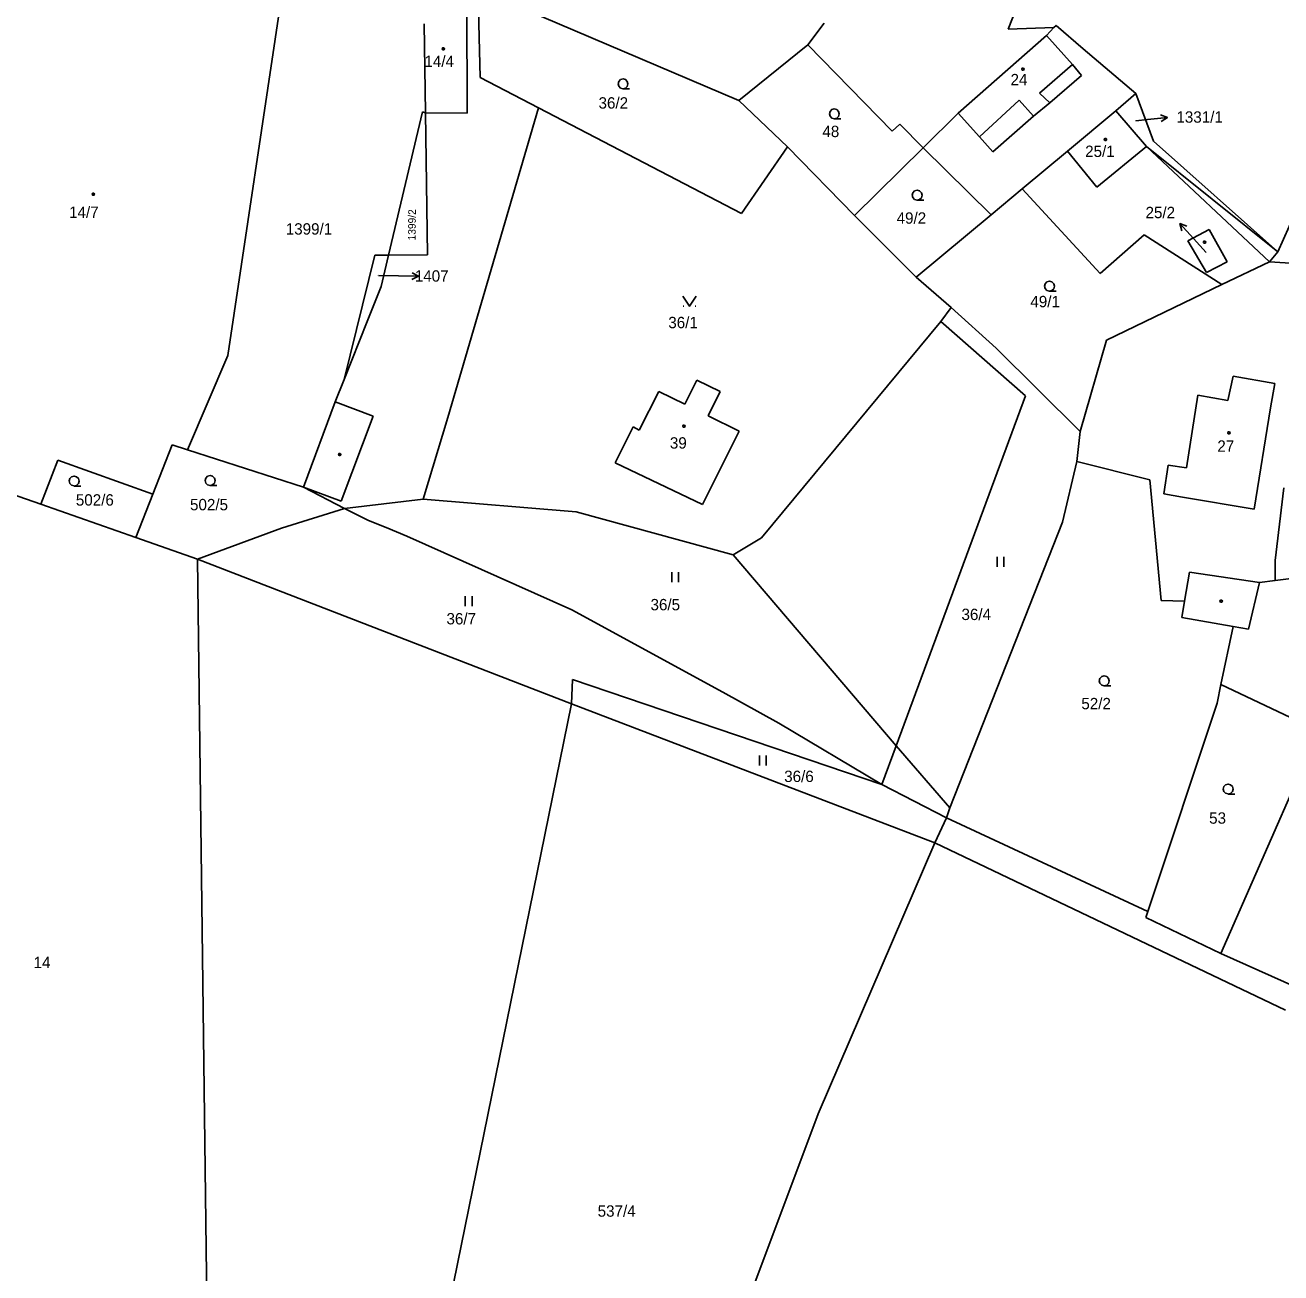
# Model space of a CAD drawing. Extents: x -845995 to -842497, y -1063614 to -1059680.
# Drawn here: x -844636.3 to -844448.3, y -1061712.9 to -1061526.1 of the extents above; entities that cross this region are included whole.
import ezdxf

# ---------------------------------------------------------------- set-up
doc = ezdxf.new("R2010")
doc.units = 0
for name, color, linetype in [('KN_HRANICE', 7, 'Continuous'), ('KN_KULTURY', 7, 'Continuous'), ('KN_PARCELY', 7, 'Continuous'), ('KN_SLUCKY', 7, 'Continuous'), ('KN_STAVEBNI', 7, 'Continuous')]:
    doc.layers.add(name, color=color, linetype=linetype)

# ---------------------------------------------------------------- blocks, each defined once
blk = doc.blocks.new('304')
blk.add_lwpolyline([(0, 0), (-0.38, 0.1), (-0.65, 0.37), (-0.75, 0.74), (-0.65, 1.11), (-0.38, 1.38), (-0.01, 1.48), (0.36, 1.38), (0.63, 1.11), (0.73, 0.73), (0.63, 0.35), (0.36, 0.08), (-0.02, -0.02), (0.98, -0.02)])
blk = doc.blocks.new('306')
for p, q in [((-0.5, 1.5), (-0.5, 0)), ((0.5, 0), (0.5, 1.5))]:
    blk.add_line(p, q)
blk = doc.blocks.new('314')
for p, q in [((-0.95, 0), (-0.85, 0)), ((0.85, 0), (0.95, 0))]:
    blk.add_line(p, q)
blk.add_lwpolyline([(-1, 1.5), (0, 0), (1, 1.5)])
blk = doc.blocks.new('NAHRADNI_SYMBOL')
blk.add_lwpolyline([(0.09, 0.15), (0.18, 0), (0.09, -0.15), (-0.09, -0.15), (-0.18, 0), (-0.09, 0.15), (0.09, 0.15)])
blk = doc.blocks.new('10292')
blk.add_line((0, 3), (0, 0))
blk.add_lwpolyline([(-0.5, 2), (0, 3), (0.5, 2)])
blk = doc.blocks.new('402')
blk.add_lwpolyline([(0.09, 0.15), (0.18, 0), (0.09, -0.15), (-0.09, -0.15), (-0.18, 0), (-0.09, 0.15), (0.09, 0.15)])

msp = doc.modelspace()

# ---------------------------------------------------------------- linework, layer by layer
at = {"layer": 'KN_HRANICE'}
for p, q in [((-844597.26, -1061517.65), (-844605.93, -1061575.54)), ((-844568.5, -1061521.23), (-844568.15, -1061533.97)), ((-844487.27, -1061521.98), (-844489.14, -1061526.71)), ((-844576.55, -1061525.94), (-844576.36, -1061539.23)), ((-844529.43, -1061537.42), (-844559.01, -1061524.82)), ((-844516.66, -1061525.83), (-844519.11, -1061529.08)), ((-844482.29, -1061526.47), (-844481.96, -1061526.18)), ((-844481.96, -1061526.18), (-844477.9, -1061529.66)), ((-844483.41, -1061527.66), (-844496.62, -1061539.27)), ((-844489.14, -1061526.71), (-844482.29, -1061526.47)), ((-844483.41, -1061527.66), (-844482.29, -1061526.47)), ((-844519.11, -1061529.08), (-844529.43, -1061537.42)), ((-844506.52, -1061542.01), (-844519.11, -1061529.08)), ((-844470, -1061536.35), (-844477.9, -1061529.66)), ((-844568.15, -1061533.97), (-844559.45, -1061538.5)), ((-844522.18, -1061544.31), (-844529.43, -1061537.42)), ((-844473.01, -1061538.94), (-844470, -1061536.35)), ((-844470, -1061536.35), (-844467.4, -1061543.5)), ((-844581.88, -1061560.53), (-844576.8, -1061539.11)), ((-844576.8, -1061539.11), (-844576.36, -1061539.23)), ((-844576.36, -1061539.23), (-844576.07, -1061560.49)), ((-844559.45, -1061538.5), (-844573, -1061584.86)), ((-844559.45, -1061538.5), (-844529.07, -1061554.3)), ((-844496.62, -1061539.27), (-844501.88, -1061544.47)), ((-844473.01, -1061538.94), (-844480.27, -1061544.97)), ((-844473.01, -1061538.94), (-844468.42, -1061544.28)), ((-844505.36, -1061540.96), (-844506.52, -1061542.01)), ((-844501.88, -1061544.47), (-844505.36, -1061540.96)), ((-844529.07, -1061554.3), (-844522.18, -1061544.31)), ((-844522.18, -1061544.31), (-844512.12, -1061554.6)), ((-844501.88, -1061544.47), (-844512.12, -1061554.6)), ((-844501.88, -1061544.47), (-844491.7, -1061554.5)), ((-844480.27, -1061544.97), (-844487.06, -1061550.63)), ((-844468.42, -1061544.28), (-844448.75, -1061560.05)), ((-844467.4, -1061543.5), (-844448.75, -1061560.05)), ((-844487.06, -1061550.63), (-844491.7, -1061554.5)), ((-844487.06, -1061550.63), (-844475.34, -1061563.31)), ((-844448.75, -1061560.05), (-844446.24, -1061554.35)), ((-844512.12, -1061554.6), (-844502.89, -1061563.82)), ((-844491.7, -1061554.5), (-844502.89, -1061563.82)), ((-844475.34, -1061563.31), (-844468.77, -1061557.5)), ((-844468.77, -1061557.5), (-844457.13, -1061564.94)), ((-844462.24, -1061558.4), (-844459.06, -1061556.7)), ((-844459.06, -1061556.7), (-844456.35, -1061561.53)), ((-844459.44, -1061563.15), (-844462.24, -1061558.4)), ((-844588.53, -1061579.17), (-844583.92, -1061560.55)), ((-844581.88, -1061560.53), (-844583.92, -1061560.55)), ((-844582.97, -1061565.26), (-844581.88, -1061560.53)), ((-844576.07, -1061560.49), (-844581.88, -1061560.53)), ((-844456.35, -1061561.53), (-844459.44, -1061563.15)), ((-844457.13, -1061564.94), (-844450, -1061561.52)), ((-844448.75, -1061560.05), (-844450, -1061561.52)), ((-844444.59, -1061561.88), (-844450, -1061561.52)), ((-844585.09, -1061570.48), (-844582.97, -1061565.26)), ((-844502.89, -1061563.82), (-844497.68, -1061568.39)), ((-844474.43, -1061573.26), (-844457.13, -1061564.94)), ((-844497.68, -1061568.39), (-844499.22, -1061570.46)), ((-844497.68, -1061568.39), (-844490.94, -1061574.45)), ((-844588.53, -1061579.17), (-844585.09, -1061570.48)), ((-844526.04, -1061602.85), (-844499.22, -1061570.46)), ((-844486.53, -1061581.59), (-844499.22, -1061570.46)), ((-844490.94, -1061574.45), (-844478.36, -1061586.95)), ((-844478.36, -1061586.95), (-844474.43, -1061573.26)), ((-844605.93, -1061575.54), (-844611.99, -1061589.68)), ((-844589.88, -1061582.52), (-844588.53, -1061579.17)), ((-844535.73, -1061579.25), (-844537.53, -1061582.84)), ((-844535.73, -1061579.25), (-844532.24, -1061580.97)), ((-844594.62, -1061595.27), (-844589.88, -1061582.52)), ((-844544.36, -1061586.72), (-844541.4, -1061580.94)), ((-844537.53, -1061582.84), (-844541.4, -1061580.94)), ((-844534.03, -1061584.57), (-844532.24, -1061580.97)), ((-844505.92, -1061633.98), (-844486.53, -1061581.59)), ((-844573, -1061584.86), (-844576.72, -1061597.05)), ((-844547.96, -1061591.63), (-844545.27, -1061586.24)), ((-844545.27, -1061586.24), (-844544.36, -1061586.72)), ((-844529.38, -1061586.87), (-844534.03, -1061584.57)), ((-844633.94, -1061597.82), (-844664.85, -1061586.99)), ((-844534.89, -1061597.88), (-844529.38, -1061586.87)), ((-844478.36, -1061586.95), (-844478.86, -1061591.44)), ((-844614.25, -1061588.91), (-844617.15, -1061596.33)), ((-844611.99, -1061589.68), (-844614.25, -1061588.91)), ((-844611.99, -1061589.68), (-844594.62, -1061595.27)), ((-844631.41, -1061591.24), (-844633.94, -1061597.82)), ((-844617.15, -1061596.33), (-844631.41, -1061591.24)), ((-844547.96, -1061591.63), (-844534.89, -1061597.88)), ((-844478.86, -1061591.44), (-844481.01, -1061600.53)), ((-844478.86, -1061591.44), (-844467.93, -1061594.19)), ((-844594.62, -1061595.27), (-844588.49, -1061598.47)), ((-844467.93, -1061594.19), (-844466.24, -1061612.23)), ((-844447.87, -1061595.38), (-844449.19, -1061606.24)), ((-844617.15, -1061596.33), (-844619.71, -1061602.81)), ((-844588.49, -1061598.47), (-844576.72, -1061597.05)), ((-844576.72, -1061597.05), (-844553.81, -1061598.96)), ((-844619.71, -1061602.81), (-844633.94, -1061597.82)), ((-844597.92, -1061601.39), (-844588.49, -1061598.47)), ((-844584.9, -1061600.24), (-844588.49, -1061598.47)), ((-844553.81, -1061598.96), (-844530.28, -1061605.39)), ((-844582.25, -1061601.32), (-844584.9, -1061600.24)), ((-844579.13, -1061602.62), (-844582.25, -1061601.32)), ((-844481.01, -1061600.53), (-844497.85, -1061643.25)), ((-844610.46, -1061606.05), (-844619.71, -1061602.81)), ((-844610.46, -1061606.05), (-844597.92, -1061601.39)), ((-844554.45, -1061613.63), (-844579.13, -1061602.62)), ((-844530.28, -1061605.39), (-844526.04, -1061602.85)), ((-844610.46, -1061606.05), (-844608.61, -1061754.86)), ((-844554.48, -1061627.7), (-844610.46, -1061606.05)), ((-844449.19, -1061606.24), (-844449.19, -1061609.24)), ((-844434.17, -1061607.4), (-844449.19, -1061609.24)), ((-844451.53, -1061609.53), (-844453.15, -1061616.52)), ((-844449.19, -1061609.24), (-844451.53, -1061609.53)), ((-844466.24, -1061612.23), (-844462.73, -1061612.31)), ((-844463.16, -1061614.78), (-844462.73, -1061612.31)), ((-844531.84, -1061625.95), (-844554.45, -1061613.63)), ((-844455.44, -1061616.12), (-844463.16, -1061614.78)), ((-844457.28, -1061624.8), (-844455.44, -1061616.12)), ((-844453.15, -1061616.52), (-844455.44, -1061616.12)), ((-844554.48, -1061627.7), (-844554.35, -1061624.06)), ((-844554.35, -1061624.06), (-844508.06, -1061639.77)), ((-844457.87, -1061627.58), (-844457.28, -1061624.8)), ((-844442.81, -1061631.67), (-844457.28, -1061624.8)), ((-844523.47, -1061630.59), (-844531.84, -1061625.95)), ((-844468.22, -1061658.79), (-844457.87, -1061627.58)), ((-844582.22, -1061763.64), (-844554.48, -1061627.7)), ((-844500.09, -1061648.51), (-844554.48, -1061627.7)), ((-844508.06, -1061639.77), (-844523.47, -1061630.59)), ((-844508.06, -1061639.77), (-844505.92, -1061633.98)), ((-844445.01, -1061637.13), (-844457.31, -1061665.08)), ((-844508.06, -1061639.77), (-844498.37, -1061644.75)), ((-844497.85, -1061643.25), (-844498.37, -1061644.75)), ((-844498.37, -1061644.75), (-844500.09, -1061648.51)), ((-844498.37, -1061644.75), (-844468.22, -1061658.79)), ((-844517.56, -1061689.06), (-844500.09, -1061648.51)), ((-844447.63, -1061673.57), (-844500.09, -1061648.51)), ((-844468.52, -1061659.69), (-844468.22, -1061658.79)), ((-844457.31, -1061665.08), (-844468.52, -1061659.69)), ((-844438.63, -1061673.4), (-844457.31, -1061665.08)), ((-844539.86, -1061748.43), (-844517.56, -1061689.06))]:
    msp.add_line(p, q, dxfattribs=at)
at = {"layer": 'KN_PARCELY'}
for p, q in [((-844470.04, -1061540.44), (-844468.27, -1061540.25)), ((-844459.49, -1061560.13), (-844461.41, -1061558.03)), ((-844583.39, -1061563.6), (-844580.38, -1061563.65))]:
    msp.add_line(p, q, dxfattribs=at)
at = {"layer": 'KN_SLUCKY'}
for p, q in [((-844570.1, -1061539.27), (-844570.17, -1061523.06)), ((-844483.41, -1061527.66), (-844479.49, -1061532)), ((-844484.42, -1061536.3), (-844479.49, -1061532)), ((-844478.16, -1061533.64), (-844482.92, -1061537.75)), ((-844479.49, -1061532), (-844478.16, -1061533.64)), ((-844493.43, -1061542.82), (-844487.47, -1061537.35)), ((-844487.47, -1061537.35), (-844485.35, -1061539.76)), ((-844482.92, -1061537.75), (-844484.42, -1061536.3)), ((-844576.36, -1061539.23), (-844570.1, -1061539.27)), ((-844493.43, -1061542.82), (-844496.62, -1061539.27)), ((-844482.92, -1061537.75), (-844485.35, -1061539.76)), ((-844485.35, -1061539.76), (-844491.43, -1061545.1)), ((-844491.43, -1061545.1), (-844493.43, -1061542.82)), ((-844475.84, -1061550.39), (-844480.27, -1061544.97)), ((-844468.42, -1061544.28), (-844475.84, -1061550.39)), ((-844450, -1061561.52), (-844468.42, -1061544.28)), ((-844455.44, -1061578.66), (-844456.23, -1061582.31)), ((-844449.21, -1061579.73), (-844455.44, -1061578.66)), ((-844449.84, -1061583.39), (-844449.21, -1061579.73)), ((-844589.88, -1061582.52), (-844584.19, -1061584.62)), ((-844460.74, -1061581.49), (-844462.44, -1061592.38)), ((-844456.23, -1061582.31), (-844460.74, -1061581.49)), ((-844452.33, -1061598.56), (-844449.84, -1061583.39)), ((-844584.19, -1061584.62), (-844588.96, -1061597.37)), ((-844465.16, -1061591.96), (-844465.85, -1061596.27)), ((-844462.44, -1061592.38), (-844465.16, -1061591.96)), ((-844588.96, -1061597.37), (-844594.62, -1061595.27)), ((-844463.04, -1061596.75), (-844465.85, -1061596.27)), ((-844452.33, -1061598.56), (-844463.04, -1061596.75)), ((-844530.28, -1061605.39), (-844505.92, -1061633.98)), ((-844462.73, -1061612.31), (-844461.98, -1061607.98)), ((-844451.53, -1061609.53), (-844461.98, -1061607.98)), ((-844505.92, -1061633.98), (-844497.85, -1061643.25))]:
    msp.add_line(p, q, dxfattribs=at)
at = {"layer": 'KN_STAVEBNI'}
for p, q in [((-844570.1, -1061539.27), (-844570.17, -1061523.06)), ((-844576.55, -1061525.94), (-844576.36, -1061539.23)), ((-844483.41, -1061527.66), (-844496.62, -1061539.27)), ((-844483.41, -1061527.66), (-844479.49, -1061532)), ((-844484.42, -1061536.3), (-844479.49, -1061532)), ((-844493.43, -1061542.82), (-844487.47, -1061537.35)), ((-844487.47, -1061537.35), (-844485.35, -1061539.76)), ((-844482.92, -1061537.75), (-844484.42, -1061536.3)), ((-844576.36, -1061539.23), (-844570.1, -1061539.27)), ((-844493.43, -1061542.82), (-844496.62, -1061539.27)), ((-844482.92, -1061537.75), (-844485.35, -1061539.76)), ((-844473.01, -1061538.94), (-844480.27, -1061544.97)), ((-844473.01, -1061538.94), (-844468.42, -1061544.28)), ((-844475.84, -1061550.39), (-844480.27, -1061544.97)), ((-844468.42, -1061544.28), (-844475.84, -1061550.39)), ((-844455.44, -1061578.66), (-844456.23, -1061582.31)), ((-844449.21, -1061579.73), (-844455.44, -1061578.66)), ((-844535.73, -1061579.25), (-844537.53, -1061582.84)), ((-844535.73, -1061579.25), (-844532.24, -1061580.97)), ((-844449.84, -1061583.39), (-844449.21, -1061579.73)), ((-844544.36, -1061586.72), (-844541.4, -1061580.94)), ((-844537.53, -1061582.84), (-844541.4, -1061580.94)), ((-844534.03, -1061584.57), (-844532.24, -1061580.97)), ((-844460.74, -1061581.49), (-844462.44, -1061592.38)), ((-844456.23, -1061582.31), (-844460.74, -1061581.49)), ((-844452.33, -1061598.56), (-844449.84, -1061583.39)), ((-844547.96, -1061591.63), (-844545.27, -1061586.24)), ((-844545.27, -1061586.24), (-844544.36, -1061586.72)), ((-844529.38, -1061586.87), (-844534.03, -1061584.57)), ((-844534.89, -1061597.88), (-844529.38, -1061586.87)), ((-844547.96, -1061591.63), (-844534.89, -1061597.88)), ((-844465.16, -1061591.96), (-844465.85, -1061596.27)), ((-844462.44, -1061592.38), (-844465.16, -1061591.96)), ((-844463.04, -1061596.75), (-844465.85, -1061596.27)), ((-844452.33, -1061598.56), (-844463.04, -1061596.75))]:
    msp.add_line(p, q, dxfattribs=at)

# ---------------------------------------------------------------- block references
at = {"layer": 'KN_KULTURY'}
for name, p in [('402', (-844573.68, -1061529.66)), ('402', (-844486.93, -1061532.7)), ('304', (-844546.77, -1061535.64)), ('304', (-844515.15, -1061540.13)), ('402', (-844474.57, -1061543.22)), ('NAHRADNI_SYMBOL', (-844626.08, -1061551.43)), ('304', (-844502.75, -1061552.31)), ('NAHRADNI_SYMBOL', (-844459.73, -1061558.6)), ('304', (-844482.94, -1061565.93)), ('314', (-844536.84, -1061568.2)), ('402', (-844537.67, -1061586.12)), ('402', (-844456.09, -1061587.13)), ('402', (-844589.19, -1061590.38)), ('304', (-844628.94, -1061595.08)), ('304', (-844608.58, -1061595.02)), ('306', (-844490.28, -1061607.18)), ('306', (-844539, -1061609.51)), ('306', (-844569.89, -1061613.07)), ('402', (-844457.25, -1061612.33)), ('304', (-844474.74, -1061625)), ('306', (-844525.86, -1061636.94)), ('304', (-844456.2, -1061641.19))]:
    msp.add_blockref(name, p, dxfattribs=at)
at = {"layer": 'KN_PARCELY'}
for p, rotation in [((-844468.27, -1061540.25), -83.77704700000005), ((-844461.41, -1061558.03), 42.341581), ((-844580.38, -1061563.65), -90.99631500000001)]:
    msp.add_blockref('10292', p, dxfattribs=dict(at, rotation=rotation))

# ---------------------------------------------------------------- texts
for s, height, p in [('14/4', 1.7, (-844576.51, -1061532.38)), ('24', 1.7, (-844488.78, -1061535.12)), ('36/2', 1.7, (-844550.45, -1061538.61)), ('1331/1', 1.7, (-844463.95, -1061540.72)), ('48', 1.7, (-844516.94, -1061542.88)), ('1331/1', 0.1, (-844470.32, -1061540.44)), ('25/1', 1.7, (-844477.61, -1061545.85)), ('14/7', 1.7, (-844629.7, -1061554.97)), ('49/2', 1.7, (-844505.83, -1061555.84)), ('25/2', 1.7, (-844468.57, -1061555.01)), ('1399/1', 1.7, (-844597.27, -1061557.47)), ('25/2', 0.1, (-844459.69, -1061560.13)), ('1407', 0.1, (-844583.59, -1061563.65)), ('1407', 1.7, (-844577.95, -1061564.51)), ('49/1', 1.7, (-844485.81, -1061568.34)), ('36/1', 1.7, (-844540.01, -1061571.48)), ('39', 1.7, (-844539.77, -1061589.5)), ('27', 1.7, (-844457.82, -1061589.97)), ('502/6', 1.7, (-844628.69, -1061598.03)), ('502/5', 1.7, (-844611.6, -1061598.73)), ('36/5', 1.7, (-844542.67, -1061613.7)), ('36/7', 1.7, (-844573.21, -1061615.81)), ('36/4', 1.7, (-844496.12, -1061615.16)), ('52/2', 1.7, (-844478.18, -1061628.51)), ('36/6', 1.7, (-844522.66, -1061639.4)), ('53', 1.7, (-844459.05, -1061645.64)), ('14', 1.7, (-844635.02, -1061667.26)), ('537/4', 1.7, (-844550.58, -1061704.46))]:
    msp.add_text(s, height=height, dxfattribs=at).set_placement(p)
msp.add_text('1399/2', height=1.14, rotation=89.496, dxfattribs=at).set_placement((-844577.83, -1061558.34))

doc.saveas('drawing.dxf')
